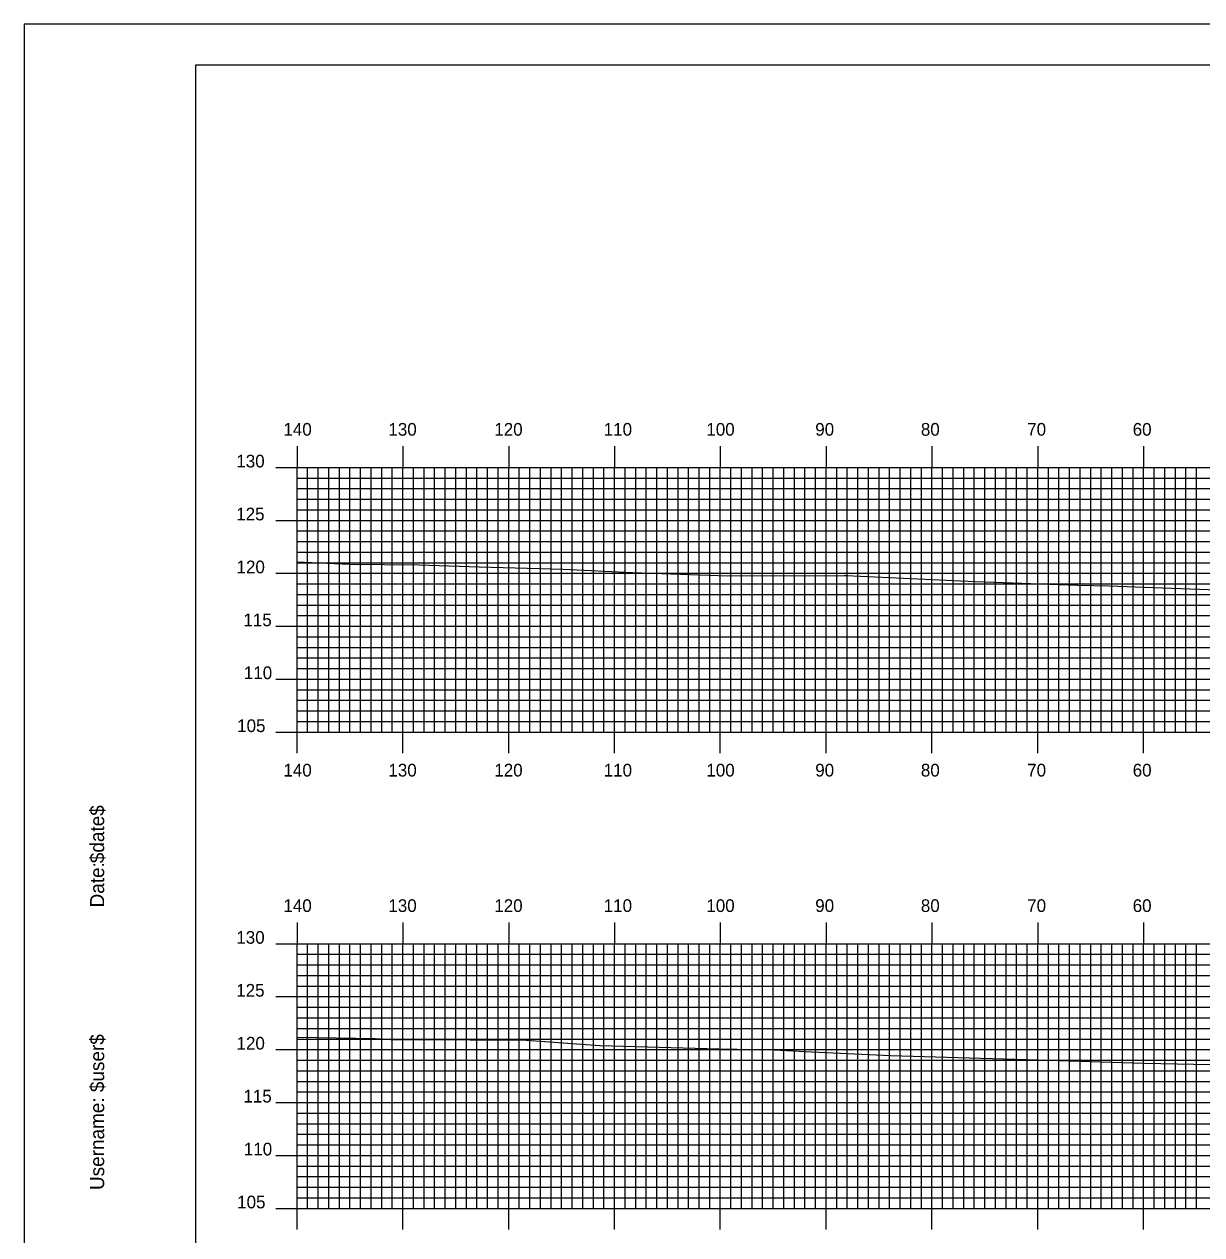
# Model space of a CAD drawing. Extents: x 1771629 to 1771972, y 442591 to 442811.
# Drawn here: x 1771628.8 to 1771740.1, y 442696.2 to 442810.5 of the extents above; entities that cross this region are included whole.
import ezdxf

# ---------------------------------------------------------------- set-up
doc = ezdxf.new("R2010")
doc.units = 0
for name, color, linetype in [('BORDER', 7, 'Continuous'), ('H_V ANNOTATION', 7, 'Continuous'), ('MAJOR', 7, 'Continuous'), ('MINOR', 7, 'Continuous'), ('PLOT BOUNDARY', 7, 'Continuous'), ('S_Roadway_Centerline', 7, 'Continuous')]:
    doc.layers.add(name, color=color, linetype=linetype)

msp = doc.modelspace()

# ---------------------------------------------------------------- linework, layer by layer
at = {"layer": 'BORDER'}
msp.add_lwpolyline([(1771644.98, 442596.67), (1771964.98, 442596.67), (1771964.98, 442806.67), (1771644.98, 442806.67)], close=True, dxfattribs=at)
at = {"layer": 'MAJOR'}
for p, q in [((1771654.58, 442770.67), (1771654.58, 442768.67)), ((1771664.58, 442770.67), (1771664.58, 442768.67)), ((1771674.58, 442770.67), (1771674.58, 442768.67)), ((1771684.58, 442770.67), (1771684.58, 442768.67)), ((1771694.58, 442770.67), (1771694.58, 442768.67)), ((1771704.58, 442770.67), (1771704.58, 442768.67)), ((1771714.58, 442770.67), (1771714.58, 442768.67)), ((1771724.58, 442770.67), (1771724.58, 442768.67)), ((1771734.58, 442770.67), (1771734.58, 442768.67)), ((1771652.58, 442768.67), (1771654.58, 442768.67)), ((1771654.58, 442768.67), (1771934.58, 442768.67)), ((1771654.58, 442743.67), (1771654.58, 442768.67)), ((1771654.58, 442743.67), (1771654.58, 442768.67)), ((1771654.58, 442768.67), (1771934.58, 442768.67)), ((1771664.58, 442743.67), (1771664.58, 442768.67)), ((1771674.58, 442743.67), (1771674.58, 442768.67)), ((1771684.58, 442743.67), (1771684.58, 442768.67)), ((1771694.58, 442743.67), (1771694.58, 442768.67)), ((1771704.58, 442743.67), (1771704.58, 442768.67)), ((1771714.58, 442743.67), (1771714.58, 442768.67)), ((1771724.58, 442743.67), (1771724.58, 442768.67)), ((1771734.58, 442743.67), (1771734.58, 442768.67)), ((1771652.58, 442763.67), (1771654.58, 442763.67)), ((1771654.58, 442763.67), (1771934.58, 442763.67)), ((1771652.58, 442758.67), (1771654.58, 442758.67)), ((1771654.58, 442758.67), (1771934.58, 442758.67)), ((1771652.58, 442753.67), (1771654.58, 442753.67)), ((1771654.58, 442753.67), (1771934.58, 442753.67)), ((1771652.58, 442748.67), (1771654.58, 442748.67)), ((1771654.58, 442748.67), (1771934.58, 442748.67)), ((1771652.58, 442743.67), (1771654.58, 442743.67)), ((1771654.58, 442743.67), (1771934.58, 442743.67)), ((1771654.58, 442743.67), (1771934.58, 442743.67)), ((1771654.58, 442741.66), (1771654.58, 442743.67)), ((1771664.58, 442741.66), (1771664.58, 442743.67)), ((1771674.58, 442741.66), (1771674.58, 442743.67)), ((1771684.58, 442741.66), (1771684.58, 442743.67)), ((1771694.58, 442741.66), (1771694.58, 442743.67)), ((1771704.58, 442741.66), (1771704.58, 442743.67)), ((1771714.58, 442741.66), (1771714.58, 442743.67)), ((1771724.58, 442741.66), (1771724.58, 442743.67)), ((1771734.58, 442741.66), (1771734.58, 442743.67)), ((1771654.58, 442725.67), (1771654.58, 442723.67)), ((1771664.58, 442725.67), (1771664.58, 442723.67)), ((1771674.58, 442725.67), (1771674.58, 442723.67)), ((1771684.58, 442725.67), (1771684.58, 442723.67)), ((1771694.58, 442725.67), (1771694.58, 442723.67)), ((1771704.58, 442725.67), (1771704.58, 442723.67)), ((1771714.58, 442725.67), (1771714.58, 442723.67)), ((1771724.58, 442725.67), (1771724.58, 442723.67)), ((1771734.58, 442725.67), (1771734.58, 442723.67)), ((1771652.58, 442723.67), (1771654.58, 442723.67)), ((1771654.58, 442723.67), (1771934.58, 442723.67)), ((1771654.58, 442698.67), (1771654.58, 442723.67)), ((1771654.58, 442698.67), (1771654.58, 442723.67)), ((1771654.58, 442723.67), (1771934.58, 442723.67)), ((1771664.58, 442698.67), (1771664.58, 442723.67)), ((1771674.58, 442698.67), (1771674.58, 442723.67)), ((1771684.58, 442698.67), (1771684.58, 442723.67)), ((1771694.58, 442698.67), (1771694.58, 442723.67)), ((1771704.58, 442698.67), (1771704.58, 442723.67)), ((1771714.58, 442698.67), (1771714.58, 442723.67)), ((1771724.58, 442698.67), (1771724.58, 442723.67)), ((1771734.58, 442698.67), (1771734.58, 442723.67)), ((1771652.58, 442718.67), (1771654.58, 442718.67)), ((1771654.58, 442718.67), (1771934.58, 442718.67)), ((1771652.58, 442713.67), (1771654.58, 442713.67)), ((1771654.58, 442713.67), (1771934.58, 442713.67)), ((1771652.58, 442708.67), (1771654.58, 442708.67)), ((1771654.58, 442708.67), (1771934.58, 442708.67)), ((1771652.58, 442703.67), (1771654.58, 442703.67)), ((1771654.58, 442703.67), (1771934.58, 442703.67)), ((1771652.58, 442698.67), (1771654.58, 442698.67)), ((1771654.58, 442698.67), (1771934.58, 442698.67)), ((1771654.58, 442698.67), (1771934.58, 442698.67)), ((1771654.58, 442696.66), (1771654.58, 442698.67)), ((1771664.58, 442696.66), (1771664.58, 442698.67)), ((1771674.58, 442696.66), (1771674.58, 442698.67)), ((1771684.58, 442696.66), (1771684.58, 442698.67)), ((1771694.58, 442696.66), (1771694.58, 442698.67)), ((1771704.58, 442696.66), (1771704.58, 442698.67)), ((1771714.58, 442696.66), (1771714.58, 442698.67)), ((1771724.58, 442696.66), (1771724.58, 442698.67)), ((1771734.58, 442696.66), (1771734.58, 442698.67))]:
    msp.add_line(p, q, dxfattribs=at)
at = {"layer": 'MINOR'}
for p, q in [((1771654.58, 442767.67), (1771934.58, 442767.67)), ((1771654.58, 442767.67), (1771656.58, 442767.67)), ((1771655.58, 442743.67), (1771655.58, 442768.67)), ((1771656.58, 442743.67), (1771656.58, 442768.67)), ((1771657.58, 442743.67), (1771657.58, 442768.67)), ((1771658.58, 442743.67), (1771658.58, 442768.67)), ((1771659.58, 442743.67), (1771659.58, 442768.67)), ((1771660.58, 442743.67), (1771660.58, 442768.67)), ((1771661.58, 442743.67), (1771661.58, 442768.67)), ((1771662.58, 442743.67), (1771662.58, 442768.67)), ((1771663.58, 442743.67), (1771663.58, 442768.67)), ((1771665.58, 442743.67), (1771665.58, 442768.67)), ((1771666.58, 442743.67), (1771666.58, 442768.67)), ((1771667.58, 442743.67), (1771667.58, 442768.67)), ((1771668.58, 442743.67), (1771668.58, 442768.67)), ((1771669.58, 442743.67), (1771669.58, 442768.67)), ((1771670.58, 442743.67), (1771670.58, 442768.67)), ((1771671.58, 442743.67), (1771671.58, 442768.67)), ((1771672.58, 442743.67), (1771672.58, 442768.67)), ((1771673.58, 442743.67), (1771673.58, 442768.67)), ((1771675.58, 442743.67), (1771675.58, 442768.67)), ((1771676.58, 442743.67), (1771676.58, 442768.67)), ((1771677.58, 442743.67), (1771677.58, 442768.67)), ((1771678.58, 442743.67), (1771678.58, 442768.67)), ((1771679.58, 442743.67), (1771679.58, 442768.67)), ((1771680.58, 442743.67), (1771680.58, 442768.67)), ((1771681.58, 442743.67), (1771681.58, 442768.67)), ((1771682.58, 442743.67), (1771682.58, 442768.67)), ((1771683.58, 442743.67), (1771683.58, 442768.67)), ((1771685.58, 442743.67), (1771685.58, 442768.67)), ((1771686.58, 442743.67), (1771686.58, 442768.67)), ((1771687.58, 442743.67), (1771687.58, 442768.67)), ((1771688.58, 442743.67), (1771688.58, 442768.67)), ((1771689.58, 442743.67), (1771689.58, 442768.67)), ((1771690.58, 442743.67), (1771690.58, 442768.67)), ((1771691.58, 442743.67), (1771691.58, 442768.67)), ((1771692.58, 442743.67), (1771692.58, 442768.67)), ((1771693.58, 442743.67), (1771693.58, 442768.67)), ((1771695.58, 442743.67), (1771695.58, 442768.67)), ((1771696.58, 442743.67), (1771696.58, 442768.67)), ((1771697.58, 442743.67), (1771697.58, 442768.67)), ((1771698.58, 442743.67), (1771698.58, 442768.67)), ((1771699.58, 442743.67), (1771699.58, 442768.67)), ((1771700.58, 442743.67), (1771700.58, 442768.67)), ((1771701.58, 442743.67), (1771701.58, 442768.67)), ((1771702.58, 442743.67), (1771702.58, 442768.67)), ((1771703.58, 442743.67), (1771703.58, 442768.67)), ((1771705.58, 442743.67), (1771705.58, 442768.67)), ((1771706.58, 442743.67), (1771706.58, 442768.67)), ((1771707.58, 442743.67), (1771707.58, 442768.67)), ((1771708.58, 442743.67), (1771708.58, 442768.67)), ((1771709.58, 442743.67), (1771709.58, 442768.67)), ((1771710.58, 442743.67), (1771710.58, 442768.67)), ((1771711.58, 442743.67), (1771711.58, 442768.67)), ((1771712.58, 442743.67), (1771712.58, 442768.67)), ((1771713.58, 442743.67), (1771713.58, 442768.67)), ((1771715.58, 442743.67), (1771715.58, 442768.67)), ((1771716.58, 442743.67), (1771716.58, 442768.67)), ((1771717.58, 442743.67), (1771717.58, 442768.67)), ((1771718.58, 442743.67), (1771718.58, 442768.67)), ((1771719.58, 442743.67), (1771719.58, 442768.67)), ((1771720.58, 442743.67), (1771720.58, 442768.67)), ((1771721.58, 442743.67), (1771721.58, 442768.67)), ((1771722.58, 442743.67), (1771722.58, 442768.67)), ((1771723.58, 442743.67), (1771723.58, 442768.67)), ((1771725.58, 442743.67), (1771725.58, 442768.67)), ((1771726.58, 442743.67), (1771726.58, 442768.67)), ((1771727.58, 442743.67), (1771727.58, 442768.67)), ((1771728.58, 442743.67), (1771728.58, 442768.67)), ((1771729.58, 442743.67), (1771729.58, 442768.67)), ((1771730.58, 442743.67), (1771730.58, 442768.67)), ((1771731.58, 442743.67), (1771731.58, 442768.67)), ((1771732.58, 442743.67), (1771732.58, 442768.67)), ((1771733.58, 442743.67), (1771733.58, 442768.67)), ((1771735.58, 442743.67), (1771735.58, 442768.67)), ((1771736.58, 442743.67), (1771736.58, 442768.67)), ((1771737.58, 442743.67), (1771737.58, 442768.67)), ((1771738.58, 442743.67), (1771738.58, 442768.67)), ((1771739.58, 442743.67), (1771739.58, 442768.67)), ((1771654.58, 442766.67), (1771934.58, 442766.67)), ((1771654.58, 442766.67), (1771656.58, 442766.67)), ((1771654.58, 442765.67), (1771934.58, 442765.67)), ((1771654.58, 442765.67), (1771656.58, 442765.67)), ((1771654.58, 442764.67), (1771934.58, 442764.67)), ((1771654.58, 442764.67), (1771656.58, 442764.67)), ((1771654.58, 442762.67), (1771934.58, 442762.67)), ((1771654.58, 442762.67), (1771656.58, 442762.67)), ((1771654.58, 442761.67), (1771934.58, 442761.67)), ((1771654.58, 442761.67), (1771656.58, 442761.67)), ((1771654.58, 442760.67), (1771934.58, 442760.67)), ((1771654.58, 442760.67), (1771656.58, 442760.67)), ((1771654.58, 442759.67), (1771934.58, 442759.67)), ((1771654.58, 442759.67), (1771656.58, 442759.67)), ((1771654.58, 442757.67), (1771934.58, 442757.67)), ((1771654.58, 442757.67), (1771656.58, 442757.67)), ((1771654.58, 442756.67), (1771934.58, 442756.67)), ((1771654.58, 442756.67), (1771656.58, 442756.67)), ((1771654.58, 442755.67), (1771934.58, 442755.67)), ((1771654.58, 442755.67), (1771656.58, 442755.67)), ((1771654.58, 442754.67), (1771934.58, 442754.67)), ((1771654.58, 442754.67), (1771656.58, 442754.67)), ((1771654.58, 442752.67), (1771934.58, 442752.67)), ((1771654.58, 442752.67), (1771656.58, 442752.67)), ((1771654.58, 442751.67), (1771934.58, 442751.67)), ((1771654.58, 442751.67), (1771656.58, 442751.67)), ((1771654.58, 442750.67), (1771934.58, 442750.67)), ((1771654.58, 442750.67), (1771656.58, 442750.67)), ((1771654.58, 442749.67), (1771934.58, 442749.67)), ((1771654.58, 442749.67), (1771656.58, 442749.67)), ((1771654.58, 442747.67), (1771934.58, 442747.67)), ((1771654.58, 442747.67), (1771656.58, 442747.67)), ((1771654.58, 442746.67), (1771934.58, 442746.67)), ((1771654.58, 442746.67), (1771656.58, 442746.67)), ((1771654.58, 442745.67), (1771934.58, 442745.67)), ((1771654.58, 442745.67), (1771656.58, 442745.67)), ((1771654.58, 442744.67), (1771934.58, 442744.67)), ((1771654.58, 442744.67), (1771656.58, 442744.67)), ((1771655.58, 442698.67), (1771655.58, 442723.67)), ((1771656.58, 442698.67), (1771656.58, 442723.67)), ((1771657.58, 442698.67), (1771657.58, 442723.67)), ((1771658.58, 442698.67), (1771658.58, 442723.67)), ((1771659.58, 442698.67), (1771659.58, 442723.67)), ((1771660.58, 442698.67), (1771660.58, 442723.67)), ((1771661.58, 442698.67), (1771661.58, 442723.67)), ((1771662.58, 442698.67), (1771662.58, 442723.67)), ((1771663.58, 442698.67), (1771663.58, 442723.67)), ((1771665.58, 442698.67), (1771665.58, 442723.67)), ((1771666.58, 442698.67), (1771666.58, 442723.67)), ((1771667.58, 442698.67), (1771667.58, 442723.67)), ((1771668.58, 442698.67), (1771668.58, 442723.67)), ((1771669.58, 442698.67), (1771669.58, 442723.67)), ((1771670.58, 442698.67), (1771670.58, 442723.67)), ((1771671.58, 442698.67), (1771671.58, 442723.67)), ((1771672.58, 442698.67), (1771672.58, 442723.67)), ((1771673.58, 442698.67), (1771673.58, 442723.67)), ((1771675.58, 442698.67), (1771675.58, 442723.67)), ((1771676.58, 442698.67), (1771676.58, 442723.67)), ((1771677.58, 442698.67), (1771677.58, 442723.67)), ((1771678.58, 442698.67), (1771678.58, 442723.67)), ((1771679.58, 442698.67), (1771679.58, 442723.67)), ((1771680.58, 442698.67), (1771680.58, 442723.67)), ((1771681.58, 442698.67), (1771681.58, 442723.67)), ((1771682.58, 442698.67), (1771682.58, 442723.67)), ((1771683.58, 442698.67), (1771683.58, 442723.67)), ((1771685.58, 442698.67), (1771685.58, 442723.67)), ((1771686.58, 442698.67), (1771686.58, 442723.67)), ((1771687.58, 442698.67), (1771687.58, 442723.67)), ((1771688.58, 442698.67), (1771688.58, 442723.67)), ((1771689.58, 442698.67), (1771689.58, 442723.67)), ((1771690.58, 442698.67), (1771690.58, 442723.67)), ((1771691.58, 442698.67), (1771691.58, 442723.67)), ((1771692.58, 442698.67), (1771692.58, 442723.67)), ((1771693.58, 442698.67), (1771693.58, 442723.67)), ((1771695.58, 442698.67), (1771695.58, 442723.67)), ((1771696.58, 442698.67), (1771696.58, 442723.67)), ((1771697.58, 442698.67), (1771697.58, 442723.67)), ((1771698.58, 442698.67), (1771698.58, 442723.67)), ((1771699.58, 442698.67), (1771699.58, 442723.67)), ((1771700.58, 442698.67), (1771700.58, 442723.67)), ((1771701.58, 442698.67), (1771701.58, 442723.67)), ((1771702.58, 442698.67), (1771702.58, 442723.67)), ((1771703.58, 442698.67), (1771703.58, 442723.67)), ((1771705.58, 442698.67), (1771705.58, 442723.67)), ((1771706.58, 442698.67), (1771706.58, 442723.67)), ((1771707.58, 442698.67), (1771707.58, 442723.67)), ((1771708.58, 442698.67), (1771708.58, 442723.67)), ((1771709.58, 442698.67), (1771709.58, 442723.67)), ((1771710.58, 442698.67), (1771710.58, 442723.67)), ((1771711.58, 442698.67), (1771711.58, 442723.67)), ((1771712.58, 442698.67), (1771712.58, 442723.67)), ((1771713.58, 442698.67), (1771713.58, 442723.67)), ((1771715.58, 442698.67), (1771715.58, 442723.67)), ((1771716.58, 442698.67), (1771716.58, 442723.67)), ((1771717.58, 442698.67), (1771717.58, 442723.67)), ((1771718.58, 442698.67), (1771718.58, 442723.67)), ((1771719.58, 442698.67), (1771719.58, 442723.67)), ((1771720.58, 442698.67), (1771720.58, 442723.67)), ((1771721.58, 442698.67), (1771721.58, 442723.67)), ((1771722.58, 442698.67), (1771722.58, 442723.67)), ((1771723.58, 442698.67), (1771723.58, 442723.67)), ((1771725.58, 442698.67), (1771725.58, 442723.67)), ((1771726.58, 442698.67), (1771726.58, 442723.67)), ((1771727.58, 442698.67), (1771727.58, 442723.67)), ((1771728.58, 442698.67), (1771728.58, 442723.67)), ((1771729.58, 442698.67), (1771729.58, 442723.67)), ((1771730.58, 442698.67), (1771730.58, 442723.67)), ((1771731.58, 442698.67), (1771731.58, 442723.67)), ((1771732.58, 442698.67), (1771732.58, 442723.67)), ((1771733.58, 442698.67), (1771733.58, 442723.67)), ((1771735.58, 442698.67), (1771735.58, 442723.67)), ((1771736.58, 442698.67), (1771736.58, 442723.67)), ((1771737.58, 442698.67), (1771737.58, 442723.67)), ((1771738.58, 442698.67), (1771738.58, 442723.67)), ((1771739.58, 442698.67), (1771739.58, 442723.67)), ((1771654.58, 442722.67), (1771934.58, 442722.67)), ((1771654.58, 442722.67), (1771656.58, 442722.67)), ((1771654.58, 442721.67), (1771934.58, 442721.67)), ((1771654.58, 442721.67), (1771656.58, 442721.67)), ((1771654.58, 442720.67), (1771934.58, 442720.67)), ((1771654.58, 442720.67), (1771656.58, 442720.67)), ((1771654.58, 442719.67), (1771934.58, 442719.67)), ((1771654.58, 442719.67), (1771656.58, 442719.67)), ((1771654.58, 442717.67), (1771934.58, 442717.67)), ((1771654.58, 442717.67), (1771656.58, 442717.67)), ((1771654.58, 442716.67), (1771934.58, 442716.67)), ((1771654.58, 442716.67), (1771656.58, 442716.67)), ((1771654.58, 442715.67), (1771934.58, 442715.67)), ((1771654.58, 442715.67), (1771656.58, 442715.67)), ((1771654.58, 442714.67), (1771934.58, 442714.67)), ((1771654.58, 442714.67), (1771656.58, 442714.67)), ((1771654.58, 442712.67), (1771934.58, 442712.67)), ((1771654.58, 442712.67), (1771656.58, 442712.67)), ((1771654.58, 442711.67), (1771934.58, 442711.67)), ((1771654.58, 442711.67), (1771656.58, 442711.67)), ((1771654.58, 442710.67), (1771934.58, 442710.67)), ((1771654.58, 442710.67), (1771656.58, 442710.67)), ((1771654.58, 442709.67), (1771934.58, 442709.67)), ((1771654.58, 442709.67), (1771656.58, 442709.67)), ((1771654.58, 442707.67), (1771934.58, 442707.67)), ((1771654.58, 442707.67), (1771656.58, 442707.67)), ((1771654.58, 442706.67), (1771934.58, 442706.67)), ((1771654.58, 442706.67), (1771656.58, 442706.67)), ((1771654.58, 442705.67), (1771934.58, 442705.67)), ((1771654.58, 442705.67), (1771656.58, 442705.67)), ((1771654.58, 442704.67), (1771934.58, 442704.67)), ((1771654.58, 442704.67), (1771656.58, 442704.67)), ((1771654.58, 442702.67), (1771934.58, 442702.67)), ((1771654.58, 442702.67), (1771656.58, 442702.67)), ((1771654.58, 442701.67), (1771934.58, 442701.67)), ((1771654.58, 442701.67), (1771656.58, 442701.67)), ((1771654.58, 442700.67), (1771934.58, 442700.67)), ((1771654.58, 442700.67), (1771656.58, 442700.67)), ((1771654.58, 442699.67), (1771934.58, 442699.67)), ((1771654.58, 442699.67), (1771656.58, 442699.67))]:
    msp.add_line(p, q, dxfattribs=at)
at = {"layer": 'PLOT BOUNDARY'}
msp.add_lwpolyline([(1771628.79, 442590.55), (1771968.79, 442590.55), (1771968.79, 442810.55), (1771628.79, 442810.55)], close=True, dxfattribs=at)
at = {"layer": 'S_Roadway_Centerline'}
for points in [[(1771654.58, 442759.74), (1771659.55, 442759.52), (1771666.11, 442759.47), (1771671.8, 442759.28), (1771679.73, 442759.05), (1771686.31, 442758.75), (1771695.28, 442758.42), (1771706.28, 442758.45), (1771706.38, 442758.45), (1771706.47, 442758.45), (1771718.66, 442757.89), (1771728.34, 442757.56), (1771731.32, 442757.47), (1771735.5, 442757.32), (1771748.52, 442756.87)], [(1771654.58, 442714.85), (1771661.99, 442714.71), (1771663.44, 442714.63), (1771665.59, 442714.62), (1771676.26, 442714.57), (1771683.18, 442714.06), (1771694.44, 442713.73), (1771699.66, 442713.64), (1771703.23, 442713.45), (1771710.67, 442713.12), (1771723.49, 442712.74), (1771734.67, 442712.4), (1771743.96, 442712.2)]]:
    msp.add_lwpolyline(points, dxfattribs=at)

# ---------------------------------------------------------------- texts
at = {"layer": 'BORDER'}
for s, p in [('$date$', (1771636.35, 442731.28)), ('Date:', (1771636.35, 442727.1)), ('$user$', (1771636.35, 442709.65)), ('Username:', (1771636.35, 442700.4))]:
    msp.add_text(s, height=1.339, rotation=90, dxfattribs=at).set_placement(p)
at = {"layer": 'H_V ANNOTATION'}
for s, p in [('140', (1771653.29, 442771.67)), ('130', (1771663.21, 442771.67)), ('120', (1771673.22, 442771.67)), ('110', (1771683.56, 442771.67)), ('100', (1771693.26, 442771.67)), ('90', (1771703.55, 442771.67)), ('80', (1771713.53, 442771.67)), ('70', (1771723.58, 442771.67)), ('60', (1771733.55, 442771.67)), ('130', (1771648.84, 442768.67)), ('125', (1771648.83, 442763.67)), ('120', (1771648.86, 442758.67)), ('115', (1771649.51, 442753.67)), ('110', (1771649.55, 442748.67)), ('105', (1771648.92, 442743.67)), ('140', (1771653.29, 442739.47)), ('130', (1771663.21, 442739.47)), ('120', (1771673.22, 442739.47)), ('110', (1771683.56, 442739.47)), ('100', (1771693.26, 442739.47)), ('90', (1771703.55, 442739.47)), ('80', (1771713.53, 442739.47)), ('70', (1771723.58, 442739.47)), ('60', (1771733.55, 442739.47)), ('140', (1771653.29, 442726.67)), ('130', (1771663.21, 442726.67)), ('120', (1771673.22, 442726.67)), ('110', (1771683.56, 442726.67)), ('100', (1771693.26, 442726.67)), ('90', (1771703.55, 442726.67)), ('80', (1771713.53, 442726.67)), ('70', (1771723.58, 442726.67)), ('60', (1771733.55, 442726.67)), ('130', (1771648.84, 442723.67)), ('125', (1771648.83, 442718.67)), ('120', (1771648.86, 442713.67)), ('115', (1771649.51, 442708.67)), ('110', (1771649.55, 442703.67)), ('105', (1771648.92, 442698.67))]:
    msp.add_text(s, height=1.2, dxfattribs=at).set_placement(p)
at = {"layer": 'MAJOR'}
for p in [(1771654.57, 442743.67), (1771654.57, 442698.67)]:
    msp.add_text('-', height=0.012, dxfattribs=at).set_placement(p)

doc.saveas('drawing.dxf')
